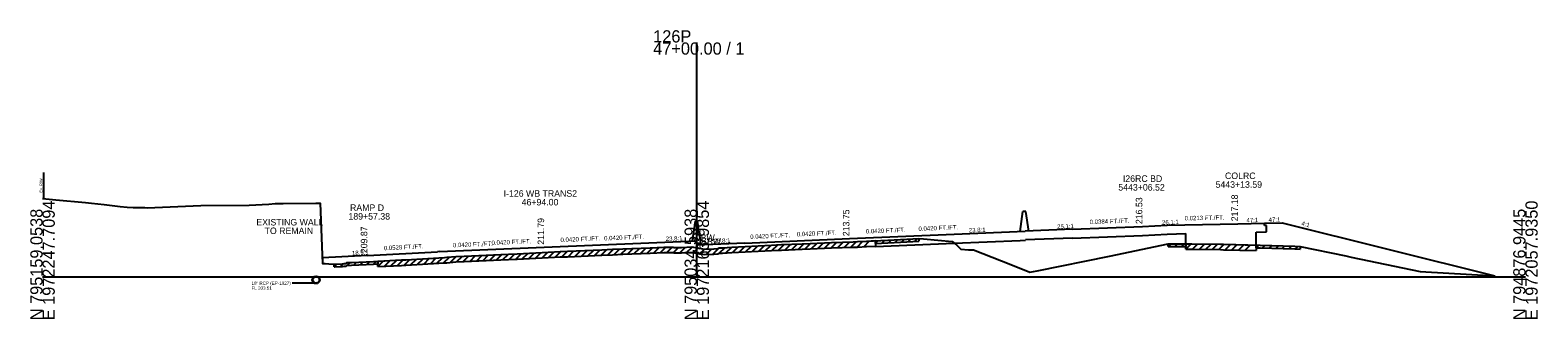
# Model space of a CAD drawing. Extents: x -161 to 1970889, y -4362 to 797231.
# Drawn here: x 997.2 to 1342.8, y 9490.3 to 9556.6 of the extents above; entities that cross this region are included whole.
import ezdxf

# ---------------------------------------------------------------- set-up
doc = ezdxf.new("R2010")
doc.units = 0
for name, color, linetype in [('RD_GPK_XS_Cell', 7, 'Continuous'), ('RD_XS_Base', 7, 'Continuous'), ('RD_XS_EarthShd', 7, 'Continuous'), ('RD_XS_ExGround', 7, 'Continuous'), ('RD_XS_ExPaveRet', 7, 'Continuous'), ('RD_XS_ExRW', 7, 'Continuous'), ('RD_XS_MedBWall', 7, 'Continuous'), ('RD_XS_Misc_Line', 7, 'Continuous'), ('RD_XS_Pave', 7, 'Continuous'), ('RD_XS_PaveOvlay', 7, 'Continuous'), ('RD_XS_PaveShd', 7, 'Continuous'), ('RD_XS_Pipe', 7, 'Continuous'), ('RD_XS_TieSlope', 7, 'Continuous'), ('RD_XS_TX_Elev_EX', 7, 'Continuous'), ('RD_XS_TX_Elev_PR', 7, 'Continuous'), ('RD_XS_TX_MkPT', 7, 'Continuous'), ('RD_XS_TX_Notes', 7, 'Continuous'), ('RD_XS_TX_Profile', 7, 'Continuous'), ('RD_XS_TX_ShdSlope', 7, 'Continuous'), ('RD_XS_TX_Slope', 7, 'Continuous'), ('RD_XS_TX_Station', 7, 'Continuous')]:
    doc.layers.add(name, color=color, linetype=linetype)

msp = doc.modelspace()

# ---------------------------------------------------------------- linework, layer by layer
at = {"layer": 'RD_GPK_XS_Cell'}
for p, q in [((1150, 9500), (1150, 9553.81)), ((1000, 9500), (1150, 9500)), ((1150, 9500), (1340, 9500))]:
    msp.add_line(p, q, dxfattribs=at)
at = {"layer": 'RD_XS_Base'}
for p, q in [((1252.16, 9509.49), (1257.88, 9509.8)), ((1257.88, 9509.8), (1262.15, 9509.89)), ((1278.22, 9510.23), (1280.66, 9510.28)), ((1280.16, 9511.75), (1280.16, 9512.31)), ((1280.66, 9511.76), (1280.16, 9511.75)), ((1280.66, 9510.28), (1280.66, 9511.76)), ((1190.95, 9506.96), (1209, 9507.72)), ((1209, 9507.72), (1224.11, 9508.35)), ((1224.11, 9508.35), (1225.39, 9508.41)), ((1236.13, 9508.87), (1225.39, 9508.44)), ((1225.39, 9508.44), (1225.39, 9508.41)), ((1236.13, 9508.87), (1252.16, 9509.49))]:
    msp.add_line(p, q, dxfattribs=at)
at = {"layer": 'RD_XS_EarthShd'}
msp.add_line((1280.16, 9512.31), (1284.21, 9512.4), dxfattribs=at)
at = {"layer": 'RD_XS_ExGround'}
for p, q in [((1300, 9504.52), (1315.84, 9501.2)), ((1315.84, 9501.2), (1332.94, 9500.22))]:
    msp.add_line(p, q, dxfattribs=at)
msp.add_lwpolyline([(1000, 9517.94), (1003.04, 9517.63), (1009.88, 9517.04), (1011.24, 9516.88), (1014.13, 9516.62), (1017.76, 9516.12), (1019.43, 9516.01), (1020.75, 9515.91), (1023.48, 9515.86), (1023.98, 9515.85), (1036.29, 9516.37), (1047.36, 9516.43), (1051.87, 9516.7), (1053.31, 9516.8), (1055.2, 9516.81), (1062.66, 9516.87), (1063.29, 9516.86), (1063.64, 9516.86), (1064.21, 9503.07), (1064.83, 9503.05), (1065.62, 9502.99), (1066.97, 9502.87), (1068.78, 9502.99), (1069.14, 9503.01), (1069.63, 9503.07), (1069.8, 9503.23), (1070.85, 9503.28), (1075.87, 9503.51), (1082.3, 9503.84), (1083.32, 9503.9), (1092.13, 9504.44), (1092.72, 9504.47), (1094.79, 9504.63), (1096.69, 9504.72), (1105.05, 9505.12), (1106.82, 9505.21), (1108.8, 9505.29), (1117.35, 9505.71), (1118.68, 9505.78), (1120.35, 9505.84), (1128.25, 9506.19), (1130.64, 9506.31), (1133.07, 9506.41), (1139.28, 9506.66), (1142.44, 9506.81), (1143.7, 9506.81), (1144.55, 9506.82), (1144.82, 9506.71), (1146.47, 9506.74), (1148.84, 9506.83), (1150, 9506.63), (1150.59, 9506.53), (1151.66, 9506.34), (1153.91, 9506.42), (1154.8, 9506.47), (1155.13, 9506.62), (1155.9, 9506.66), (1158.03, 9506.79), (1167.16, 9507.25), (1169.45, 9507.38), (1174.14, 9507.55), (1175.99, 9507.64), (1180.86, 9507.85), (1185.83, 9508.03), (1186.85, 9508.07), (1188.88, 9508.17), (1193.77, 9508.42), (1198.19, 9508.66), (1200.95, 9508.81), (1202.01, 9508.72), (1208.58, 9508.06), (1209.53, 9507.31), (1210.55, 9506.33), (1212.3, 9506.19), (1213.41, 9506.18), (1221.99, 9502.82), (1226.4, 9501.07), (1228.07, 9501.38), (1244.61, 9504.7), (1258.1, 9507.56), (1258.94, 9507.56), (1262.07, 9507.57), (1263.51, 9507.54), (1270.08, 9507.48), (1270.75, 9507.46), (1279.16, 9507.25), (1287.12, 9507), (1288.35, 9506.96), (1298.84, 9504.76), (1300, 9504.52)], dxfattribs=at)
at = {"layer": 'RD_XS_ExPaveRet'}
for p, q in [((1169.45, 9506.13), (1174.14, 9506.3)), ((1174.14, 9506.3), (1175.99, 9506.39)), ((1175.99, 9506.39), (1180.86, 9506.6)), ((1180.86, 9506.6), (1185.83, 9506.78)), ((1185.83, 9506.78), (1186.85, 9506.82)), ((1186.85, 9506.82), (1188.88, 9506.92)), ((1188.88, 9506.92), (1190.95, 9507.03)), ((1190.95, 9508.28), (1190.95, 9507.03)), ((1190.95, 9507.65), (1190.95, 9508.28)), ((1190.95, 9507.65), (1193.77, 9507.79)), ((1193.77, 9507.79), (1198.19, 9508.04)), ((1198.19, 9508.04), (1200.95, 9508.19)), ((1200.95, 9508.81), (1200.95, 9508.19)), ((1258.1, 9506.94), (1258.1, 9507.56)), ((1258.1, 9506.94), (1258.94, 9506.94)), ((1258.94, 9506.94), (1262.07, 9506.94)), ((1262.07, 9506.94), (1262.15, 9506.94)), ((1262.15, 9506.32), (1262.15, 9507.57)), ((1262.15, 9507.57), (1262.15, 9506.94)), ((1262.15, 9506.32), (1263.51, 9506.29)), ((1263.51, 9506.29), (1270.08, 9506.23)), ((1278.22, 9507.28), (1278.22, 9506.03)), ((1278.22, 9506.65), (1278.22, 9507.28)), ((1278.22, 9506.65), (1279.16, 9506.63)), ((1279.16, 9506.63), (1287.12, 9506.37)), ((1287.12, 9506.37), (1288.35, 9506.33)), ((1288.35, 9506.96), (1288.35, 9506.33)), ((1066.84, 9502.26), (1066.84, 9502.88)), ((1070.85, 9502.66), (1075.87, 9502.88)), ((1075.87, 9502.88), (1076.87, 9502.94)), ((1076.87, 9502.31), (1076.87, 9503.56)), ((1076.87, 9503.56), (1076.87, 9502.94)), ((1083.32, 9502.65), (1092.13, 9503.19)), ((1092.13, 9503.19), (1092.72, 9503.22)), ((1092.72, 9503.22), (1094.79, 9503.38)), ((1094.79, 9503.38), (1096.69, 9503.47)), ((1096.69, 9503.47), (1105.05, 9503.87)), ((1105.05, 9503.87), (1106.82, 9503.96)), ((1106.82, 9503.96), (1108.8, 9504.04)), ((1108.8, 9504.04), (1117.35, 9504.46)), ((1117.35, 9504.46), (1118.68, 9504.53)), ((1118.68, 9504.53), (1120.35, 9504.59)), ((1120.35, 9504.59), (1128.25, 9504.94)), ((1128.25, 9504.94), (1130.64, 9505.06)), ((1130.64, 9505.06), (1133.07, 9505.16)), ((1133.07, 9505.16), (1139.28, 9505.41)), ((1139.28, 9505.41), (1142.44, 9505.56)), ((1142.44, 9505.56), (1143.7, 9505.56)), ((1143.7, 9505.56), (1144.55, 9505.57)), ((1144.55, 9505.57), (1144.82, 9505.46)), ((1144.82, 9505.46), (1146.47, 9505.49)), ((1146.47, 9505.49), (1148.84, 9505.58)), ((1148.84, 9505.58), (1150, 9505.38)), ((1150, 9505.38), (1150.59, 9505.28)), ((1150.59, 9505.28), (1151.66, 9505.09)), ((1151.66, 9505.09), (1153.91, 9505.17)), ((1153.91, 9505.17), (1154.8, 9505.22)), ((1154.8, 9505.22), (1155.13, 9505.37)), ((1155.13, 9505.37), (1155.9, 9505.41)), ((1155.9, 9505.41), (1158.03, 9505.54)), ((1158.03, 9505.54), (1167.16, 9506)), ((1167.16, 9506), (1169.45, 9506.13)), ((1270.08, 9506.23), (1270.75, 9506.21)), ((1270.75, 9506.21), (1278.22, 9506.03)), ((1066.84, 9502.26), (1066.97, 9502.25)), ((1066.97, 9502.25), (1068.78, 9502.36)), ((1068.78, 9502.36), (1069.14, 9502.39)), ((1069.14, 9502.39), (1069.63, 9502.44)), ((1069.63, 9502.44), (1069.8, 9502.6)), ((1069.8, 9502.6), (1070.85, 9502.66)), ((1076.87, 9502.31), (1082.3, 9502.59)), ((1082.3, 9502.59), (1083.32, 9502.65))]:
    msp.add_line(p, q, dxfattribs=at)
at = {"layer": 'RD_XS_ExRW'}
msp.add_line((1000.22, 9523.91), (1000.22, 9517.91), dxfattribs=at)
at = {"layer": 'RD_XS_MedBWall'}
for p, q in [((1224.11, 9510.39), (1224.78, 9514.94)), ((1225.46, 9514.94), (1224.78, 9514.94)), ((1226.11, 9510.49), (1225.46, 9514.94)), ((1149, 9508.22), (1149.67, 9512.76)), ((1149.67, 9512.76), (1150.19, 9512.76)), ((1151, 9507.32), (1150.19, 9512.76))]:
    msp.add_line(p, q, dxfattribs=at)
at = {"layer": 'RD_XS_Misc_Line'}
for p, q in [((1128.07, 9504.93), (1129.39, 9506.25)), ((1129.58, 9505.01), (1130.9, 9506.32)), ((1131.08, 9505.08), (1132.39, 9506.38)), ((1132.59, 9505.14), (1133.89, 9506.44)), ((1134.09, 9505.2), (1135.4, 9506.5)), ((1135.6, 9505.26), (1136.91, 9506.57)), ((1137.1, 9505.32), (1138.41, 9506.63)), ((1138.61, 9505.39), (1139.92, 9506.69)), ((1140.12, 9505.45), (1141.43, 9506.76)), ((1141.62, 9505.52), (1142.92, 9506.81)), ((1143.13, 9505.56), (1144.39, 9506.82)), ((1144.63, 9505.54), (1145.82, 9506.73)), ((1146.14, 9505.48), (1147.44, 9506.77)), ((1147.64, 9505.53), (1148.93, 9506.82)), ((1149.15, 9505.53), (1150.22, 9506.59)), ((1150.66, 9505.26), (1151.74, 9506.34)), ((1152.16, 9505.11), (1153.47, 9506.41)), ((1153.67, 9505.16), (1155.13, 9506.62)), ((1155.17, 9505.37), (1156.5, 9506.7)), ((1156.68, 9505.46), (1158.02, 9506.79)), ((1158.18, 9505.55), (1159.51, 9506.87)), ((1159.69, 9505.63), (1161.01, 9506.94)), ((1161.2, 9505.7), (1162.52, 9507.02)), ((1162.7, 9505.78), (1164.02, 9507.09)), ((1164.21, 9505.85), (1165.53, 9507.17)), ((1165.71, 9505.93), (1167.03, 9507.24)), ((1167.22, 9506), (1168.55, 9507.33)), ((1168.73, 9506.09), (1170.04, 9507.4)), ((1170.23, 9506.16), (1171.54, 9507.45)), ((1171.74, 9506.21), (1173.04, 9507.51)), ((1173.24, 9506.27), (1174.55, 9507.57)), ((1174.75, 9506.33), (1176.06, 9507.64)), ((1176.25, 9506.4), (1177.57, 9507.7)), ((1177.76, 9506.46), (1179.07, 9507.77)), ((1179.27, 9506.53), (1180.58, 9507.83)), ((1180.77, 9506.59), (1182.07, 9507.89)), ((1182.28, 9506.65), (1183.58, 9507.95)), ((1183.78, 9506.7), (1185.09, 9508)), ((1185.29, 9506.76), (1186.6, 9508.06)), ((1186.79, 9506.82), (1188.11, 9508.13)), ((1188.3, 9506.89), (1189.62, 9508.21)), ((1190.95, 9507.65), (1191.61, 9508.31)), ((1192.45, 9507.73), (1193.11, 9508.39)), ((1193.96, 9507.8), (1194.62, 9508.47)), ((1195.46, 9507.89), (1196.13, 9508.55)), ((1196.97, 9507.97), (1197.63, 9508.63)), ((1198.48, 9508.05), (1199.14, 9508.71)), ((1199.98, 9508.13), (1200.64, 9508.8)), ((1258.1, 9506.94), (1258.73, 9507.56)), ((1259.6, 9506.94), (1260.23, 9507.57)), ((1261.11, 9506.94), (1261.74, 9507.57)), ((1262.15, 9506.32), (1263.38, 9507.55)), ((1263.65, 9506.29), (1264.89, 9507.53)), ((1265.16, 9506.28), (1266.4, 9507.51)), ((1266.66, 9506.26), (1267.91, 9507.5)), ((1268.17, 9506.25), (1269.41, 9507.48)), ((1269.67, 9506.23), (1270.91, 9507.46)), ((1271.18, 9506.2), (1272.4, 9507.42)), ((1272.69, 9506.17), (1273.91, 9507.38)), ((1274.19, 9506.13), (1275.42, 9507.35)), ((1275.7, 9506.09), (1276.92, 9507.31)), ((1278.22, 9506.65), (1278.83, 9507.26)), ((1279.73, 9506.61), (1280.33, 9507.22)), ((1281.23, 9506.56), (1281.84, 9507.17)), ((1282.74, 9506.51), (1283.35, 9507.12)), ((1284.24, 9506.47), (1284.85, 9507.07)), ((1285.75, 9506.42), (1286.36, 9507.02)), ((1287.26, 9506.37), (1287.86, 9506.98)), ((1066.84, 9502.26), (1067.48, 9502.91)), ((1068.34, 9502.34), (1069.01, 9503)), ((1069.85, 9502.6), (1070.51, 9503.27)), ((1071.35, 9502.68), (1072.01, 9503.34)), ((1072.86, 9502.75), (1073.52, 9503.4)), ((1074.36, 9502.82), (1075.02, 9503.47)), ((1075.87, 9502.88), (1076.53, 9503.54)), ((1076.87, 9502.31), (1078.2, 9503.63)), ((1078.38, 9502.39), (1079.7, 9503.71)), ((1079.89, 9502.47), (1081.21, 9503.78)), ((1081.39, 9502.54), (1082.72, 9503.86)), ((1082.9, 9502.62), (1084.23, 9503.95)), ((1084.4, 9502.71), (1085.74, 9504.04)), ((1085.91, 9502.8), (1087.25, 9504.14)), ((1087.41, 9502.9), (1088.75, 9504.23)), ((1088.92, 9502.99), (1090.26, 9504.32)), ((1090.43, 9503.08), (1091.76, 9504.41)), ((1091.93, 9503.17), (1093.28, 9504.51)), ((1093.44, 9503.28), (1094.8, 9504.63)), ((1094.94, 9503.39), (1096.26, 9504.7)), ((1096.45, 9503.46), (1097.77, 9504.77)), ((1097.95, 9503.53), (1099.27, 9504.84)), ((1099.46, 9503.6), (1100.78, 9504.92)), ((1100.97, 9503.67), (1102.28, 9504.99)), ((1102.47, 9503.75), (1103.79, 9505.06)), ((1103.98, 9503.82), (1105.3, 9505.13)), ((1105.48, 9503.89), (1106.8, 9505.2)), ((1106.99, 9503.96), (1108.3, 9505.27)), ((1108.49, 9504.03), (1109.81, 9505.34)), ((1110, 9504.1), (1111.32, 9505.42)), ((1111.51, 9504.17), (1112.83, 9505.49)), ((1113.01, 9504.25), (1114.33, 9505.56)), ((1114.52, 9504.32), (1115.84, 9505.63)), ((1116.02, 9504.39), (1117.34, 9505.71)), ((1117.53, 9504.47), (1118.85, 9505.79)), ((1119.04, 9504.54), (1120.34, 9505.84)), ((1120.54, 9504.6), (1121.85, 9505.91)), ((1122.05, 9504.67), (1123.36, 9505.97)), ((1123.55, 9504.73), (1124.86, 9506.04)), ((1125.06, 9504.8), (1126.37, 9506.11)), ((1126.56, 9504.86), (1127.88, 9506.17))]:
    msp.add_line(p, q, dxfattribs=at)
at = {"layer": 'RD_XS_Pave'}
for p, q in [((1185, 9508.75), (1209, 9509.76)), ((1236.13, 9510.91), (1252.16, 9511.53)), ((1257.84, 9511.83), (1274.07, 9512.18)), ((1091, 9505.78), (1115, 9506.79)), ((1115, 9506.79), (1139, 9507.8)), ((1161, 9507.74), (1185, 9508.75)), ((1074.47, 9504.87), (1090.52, 9505.72))]:
    msp.add_line(p, q, dxfattribs=at)
at = {"layer": 'RD_XS_PaveOvlay'}
for p, q in [((1262.15, 9507.57), (1262.15, 9509.89)), ((1278.22, 9507.28), (1278.22, 9510.23)), ((1128.25, 9506.19), (1130.64, 9506.31)), ((1130.64, 9506.31), (1133.07, 9506.41)), ((1133.07, 9506.41), (1139.28, 9506.66)), ((1139.28, 9506.66), (1142.44, 9506.81)), ((1142.44, 9506.81), (1143.7, 9506.81)), ((1143.7, 9506.81), (1144.55, 9506.82)), ((1144.55, 9506.82), (1144.82, 9506.71)), ((1144.82, 9506.71), (1146.47, 9506.74)), ((1146.47, 9506.74), (1148.84, 9506.83)), ((1148.84, 9506.83), (1150, 9506.63)), ((1150, 9506.63), (1150.59, 9506.53)), ((1150.59, 9506.53), (1151.66, 9506.34)), ((1151.66, 9506.34), (1153.91, 9506.42)), ((1153.91, 9506.42), (1154.8, 9506.47)), ((1154.8, 9506.47), (1155.13, 9506.62)), ((1155.13, 9506.62), (1155.9, 9506.66)), ((1155.9, 9506.66), (1158.03, 9506.79)), ((1158.03, 9506.79), (1167.16, 9507.25)), ((1167.16, 9507.25), (1169.45, 9507.38)), ((1169.45, 9507.38), (1174.14, 9507.55)), ((1174.14, 9507.55), (1175.99, 9507.64)), ((1175.99, 9507.64), (1180.86, 9507.85)), ((1180.86, 9507.85), (1185.83, 9508.03)), ((1185.83, 9508.03), (1186.85, 9508.07)), ((1186.85, 9508.07), (1188.88, 9508.17)), ((1188.88, 9508.17), (1190.95, 9508.28)), ((1190.95, 9508.28), (1190.95, 9506.96)), ((1076.87, 9503.56), (1082.3, 9503.84)), ((1082.3, 9503.84), (1083.32, 9503.9)), ((1083.32, 9503.9), (1092.13, 9504.44)), ((1092.13, 9504.44), (1092.72, 9504.47)), ((1092.72, 9504.47), (1094.79, 9504.63)), ((1094.79, 9504.63), (1096.69, 9504.72)), ((1096.69, 9504.72), (1105.05, 9505.12)), ((1105.05, 9505.12), (1106.82, 9505.21)), ((1106.82, 9505.21), (1108.8, 9505.29)), ((1108.8, 9505.29), (1117.35, 9505.71)), ((1117.35, 9505.71), (1118.68, 9505.78)), ((1118.68, 9505.78), (1120.35, 9505.84)), ((1120.35, 9505.84), (1128.25, 9506.19))]:
    msp.add_line(p, q, dxfattribs=at)
for points in [[(1262.15, 9507.57), (1263.51, 9507.54), (1270.08, 9507.48), (1270.75, 9507.46), (1278.22, 9507.28)], [(1064.16, 9504.32), (1064.21, 9503.07), (1064.83, 9503.05), (1065.62, 9502.99), (1066.97, 9502.87), (1068.78, 9502.99), (1069.14, 9503.01), (1069.63, 9503.07), (1069.8, 9503.23), (1070.85, 9503.28), (1075.87, 9503.51), (1076.87, 9503.56)]]:
    msp.add_lwpolyline(points, dxfattribs=at)
at = {"layer": 'RD_XS_PaveShd'}
for p, q in [((1209, 9509.76), (1225.31, 9510.44)), ((1236.13, 9510.91), (1225.31, 9510.48)), ((1225.31, 9510.44), (1225.31, 9510.48)), ((1252.16, 9511.53), (1257.84, 9511.83)), ((1274.07, 9512.18), (1280.16, 9512.31)), ((1139, 9507.8), (1150, 9508.26)), ((1150, 9507.28), (1150, 9508.26)), ((1161, 9507.74), (1150, 9507.28)), ((1074.47, 9504.87), (1064.16, 9504.32)), ((1091, 9505.78), (1090.52, 9505.72))]:
    msp.add_line(p, q, dxfattribs=at)
at = {"layer": 'RD_XS_Pipe'}
msp.add_line((1062.2, 9498.51), (1057.2, 9498.51), dxfattribs=at)
for radius in [0.85, 0.75]:
    msp.add_circle((1062.7, 9499.26), radius, dxfattribs=at)
at = {"layer": 'RD_XS_TieSlope'}
msp.add_line((1284.21, 9512.4), (1332.94, 9500.22), dxfattribs=at)

# ---------------------------------------------------------------- texts
at = {"layer": 'RD_GPK_XS_Cell'}
for s, p in [('126P', (1140, 9553.81)), ('47+00.00 / 1', (1140, 9551.01))]:
    msp.add_text(s, height=2.8, dxfattribs=at).set_placement(p)
for s, p in [('E 1972247.7094', (1002.8, 9490)), ('E 1972163.9854', (1152.8, 9490)), ('E 1972057.9350', (1342.8, 9490)), ('N 795159.0538', (1000, 9490)), ('N 795034.5938', (1150, 9490)), ('N 794876.9445', (1340, 9490))]:
    msp.add_text(s, height=2.8, rotation=90, dxfattribs=at).set_placement(p)
at = {"layer": 'RD_XS_ExRW'}
msp.add_text('Ex. R/W ', height=0.65, rotation=90, dxfattribs=at).set_placement((999.97, 9519.3))
at = {"layer": 'RD_XS_Pipe'}
for s, p in [('18" RCP (EP-1927)', (1047.91, 9498.13)), ('FL 203.51', (1047.91, 9497.01))]:
    msp.add_text(s, height=0.75, dxfattribs=at).set_placement(p)
at = {"layer": 'RD_XS_TX_Elev_EX'}
msp.add_text('211.63', height=1, rotation=90, dxfattribs=at).set_placement((1151, 9506.63))
at = {"layer": 'RD_XS_TX_Elev_PR'}
for s, p in [(' 216.53', (1252.16, 9511.53)), (' 217.18', (1274.07, 9512.18)), (' 211.79', (1115, 9506.79)), (' 213.75', (1185, 9508.75)), (' 209.87', (1074.47, 9504.86))]:
    msp.add_text(s, height=1.5, rotation=90, dxfattribs=at).set_placement(p)
at = {"layer": 'RD_XS_TX_MkPT'}
for s, p in [('WBW', (1149, 9508.22)), ('EBW', (1151, 9507.32))]:
    msp.add_text(s, height=1.5, dxfattribs=at).set_placement(p)
at = {"layer": 'RD_XS_TX_Notes'}
for s, p in [('EXISTING WALL', (1049.02, 9511.77)), ('TO REMAIN', (1050.91, 9509.8))]:
    msp.add_text(s, height=1.5, dxfattribs=at).set_placement(p)
at = {"layer": 'RD_XS_TX_Profile'}
for s, rotation, p in [('23.8:1', 2.405, (1212.41, 9510.15)), ('26.1:1', 2.1982, (1256.69, 9511.95)), ('23.8:1', 2.405, (1142.91, 9508.21)), ('23.8:1', 2.405, (1153.91, 9507.7))]:
    msp.add_text(s, height=1, rotation=rotation, dxfattribs=at).set_placement(p)
at = {"layer": 'RD_XS_TX_ShdSlope'}
msp.add_text('47:1', height=1, rotation=1.2177, dxfattribs=at).set_placement((1281.12, 9512.58))
at = {"layer": 'RD_XS_TX_Slope'}
for s, rotation, p in [('0.0384 FT./FT.', 2.1981, (1240.1, 9512.07)), ('0.0213 FT./FT.', 1.2177, (1261.88, 9512.93)), ('47:1', 1.2177, (1276.05, 9512.48)), ('0.0420 FT./FT.', 2.405, (1162.28, 9508.67)), ('0.0420 FT./FT.', 2.405, (1172.96, 9509.25)), ('0.0420 FT./FT.', 2.405, (1188.77, 9509.91)), ('0.0420 FT./FT.', 2.405, (1200.85, 9510.51)), ('25.1:1', 2.286, (1232.64, 9511.02)), ('4:1', 344.1175, (1288.55, 9511.85)), ('0.0528 FT./FT.', 3.0213, (1078.27, 9506.06)), ('0.0420 FT./FT.', 2.405, (1094.11, 9506.74)), ('0.0420 FT./FT.', 2.405, (1102.96, 9507.28)), ('0.0420 FT./FT.', 2.405, (1118.77, 9507.95)), ('0.0420 FT./FT.', 2.405, (1128.77, 9508.32)), ('18.9:1', 3.0211, (1070.97, 9504.92))]:
    msp.add_text(s, height=1, rotation=rotation, dxfattribs=at).set_placement(p)
at = {"layer": 'RD_XS_TX_Station'}
for s, p in [('COLRC', (1271.11, 9522.43)), ('5443+06.52', (1246.65, 9519.78)), ('I26RC BD', (1247.7, 9521.78)), ('5443+13.59', (1268.95, 9520.43)), ('I-126 WB TRANS2', (1105.72, 9518.37)), ('46+94.00', (1109.85, 9516.37)), ('189+57.38', (1070.14, 9513.11)), ('RAMP D', (1070.5, 9515.11))]:
    msp.add_text(s, height=1.5, dxfattribs=at).set_placement(p)

doc.saveas('drawing.dxf')
